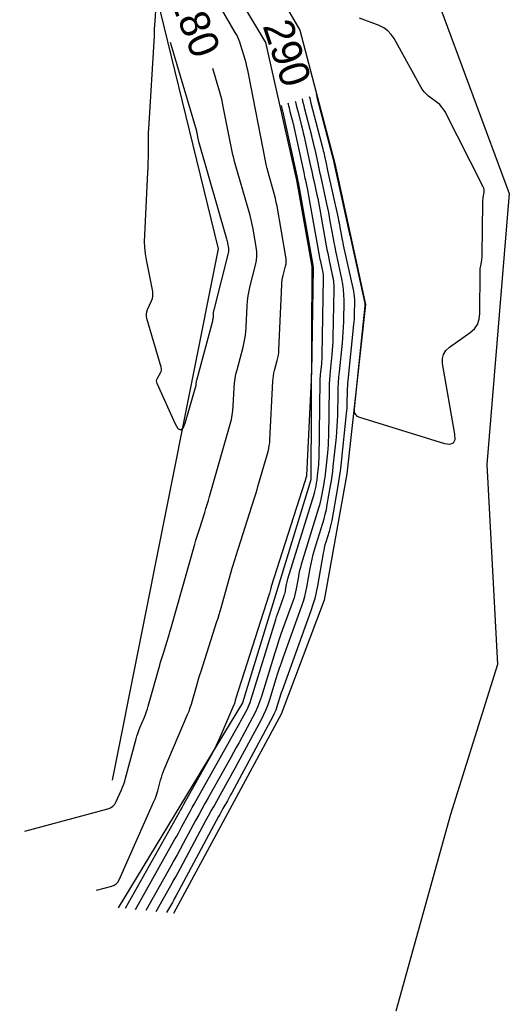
# Model space of a CAD drawing. Extents: x 1574966 to 1597594, y 720505 to 737840.
# Drawn here: x 1578135.8 to 1578233.6, y 723709.7 to 723907.8 of the extents above; entities that cross this region are included whole.
import ezdxf

# ---------------------------------------------------------------- set-up
doc = ezdxf.new("R2010")
doc.units = 0
for name, color, linetype in [('R_Contour Annot', 7, 'Continuous'), ('R_Contours', 7, 'Continuous'), ('S_BREAKLINE', 7, 'Continuous'), ('S_STREAM', 7, 'Continuous')]:
    doc.layers.add(name, color=color, linetype=linetype)

msp = doc.modelspace()

# ---------------------------------------------------------------- linework, layer by layer
at = {"layer": 'R_Contours'}
for points in [[(1578165.86, 723903.34), (1578171.09, 723885.58), (1578171.12, 723885.46), (1578171.15, 723885.35), (1578171.18, 723885.23), (1578171.2, 723885.11), (1578171.47, 723883.72), (1578171.5, 723883.61), (1578171.52, 723883.5), (1578171.55, 723883.38), (1578171.58, 723883.27), (1578177.13, 723864.01), (1578177.2, 723863.77), (1578177.25, 723863.54), (1578177.3, 723863.3), (1578177.35, 723863.07), (1578177.52, 723862.12), (1578177.54, 723861.88), (1578177.55, 723861.64), (1578177.53, 723861.41), (1578177.48, 723861.17), (1578174.57, 723849.86), (1578174.53, 723849.67), (1578174.49, 723849.48), (1578174.47, 723849.29), (1578174.46, 723849.1), (1578174.42, 723848.33), (1578174.41, 723848.13), (1578174.38, 723847.94), (1578174.35, 723847.75), (1578174.3, 723847.57), (1578171.09, 723835.72), (1578171.07, 723835.64), (1578171.05, 723835.55), (1578171.04, 723835.47), (1578171.04, 723835.38), (1578171.02, 723835.04), (1578171.01, 723834.95), (1578171, 723834.87), (1578170.98, 723834.78), (1578170.96, 723834.7), (1578168.8, 723827.12), (1578168.4, 723826.15), (1578167.97, 723825.8), (1578167.48, 723826.08), (1578166.95, 723826.99), (1578163.26, 723835.13), (1578163.17, 723835.4), (1578163.15, 723835.67), (1578163.2, 723835.94), (1578163.31, 723836.2), (1578163.91, 723837.26), (1578164.03, 723837.53), (1578164.09, 723837.8), (1578164.1, 723838.08), (1578164.04, 723838.37), (1578161.22, 723848.07), (1578161.13, 723848.53), (1578161.12, 723848.99), (1578161.19, 723849.44), (1578161.35, 723849.88), (1578162.15, 723851.65), (1578162.32, 723852.09), (1578162.41, 723852.54), (1578162.42, 723853.01), (1578162.37, 723853.48), (1578161.12, 723859.82), (1578160.92, 723861.04), (1578160.79, 723862.26), (1578160.74, 723863.49), (1578160.77, 723864.72), (1578161.41, 723877.34), (1578161.44, 723878.07), (1578161.46, 723878.79), (1578161.48, 723879.51), (1578161.49, 723880.23), (1578161.5, 723883.12), (1578161.51, 723883.84), (1578161.52, 723884.56), (1578161.55, 723885.28), (1578161.59, 723886.01), (1578162.71, 723904.54), (1578162.72, 723904.71), (1578162.73, 723904.88), (1578162.73, 723905.05), (1578162.74, 723905.23), (1578162.74, 723905.92), (1578162.75, 723906.09), (1578162.75, 723906.26), (1578162.76, 723906.44), (1578162.77, 723906.61), (1578163.05, 723910.49)], [(1578151.14, 723733.89), (1578154.21, 723734.72), (1578154.69, 723734.9), (1578155.09, 723735.17), (1578155.42, 723735.52), (1578155.67, 723735.97), (1578162.62, 723751.6), (1578162.84, 723752.12), (1578163.04, 723752.64), (1578163.21, 723753.17), (1578163.37, 723753.71), (1578163.95, 723755.88), (1578164.1, 723756.42), (1578164.27, 723756.95), (1578164.46, 723757.48), (1578164.67, 723758), (1578169.35, 723768.99), (1578169.63, 723769.67), (1578169.88, 723770.37), (1578170.12, 723771.06), (1578170.33, 723771.77), (1578171.13, 723774.61), (1578171.33, 723775.32), (1578171.54, 723776.03), (1578171.75, 723776.74), (1578171.97, 723777.44), (1578175.21, 723787.57), (1578175.43, 723788.25), (1578175.64, 723788.94), (1578175.84, 723789.62), (1578176.04, 723790.31), (1578178.28, 723798.22), (1578178.46, 723798.85), (1578178.65, 723799.48), (1578178.84, 723800.11), (1578179.04, 723800.73), (1578182.67, 723812.08), (1578182.87, 723812.69), (1578183.05, 723813.3), (1578183.23, 723813.91), (1578183.41, 723814.52), (1578185.43, 723821.56), (1578185.57, 723822.13), (1578185.68, 723822.7), (1578185.76, 723823.27), (1578185.81, 723823.86), (1578186.38, 723835.59), (1578186.42, 723836.12), (1578186.49, 723836.65), (1578186.59, 723837.17), (1578186.71, 723837.68), (1578187.27, 723839.74), (1578187.4, 723840.25), (1578187.49, 723840.78), (1578187.56, 723841.3), (1578187.6, 723841.83), (1578188.17, 723854.81), (1578188.2, 723855.28), (1578188.26, 723855.75), (1578188.34, 723856.22), (1578188.45, 723856.69), (1578188.92, 723858.53), (1578189.02, 723859), (1578189.06, 723859.46), (1578189.05, 723859.93), (1578189, 723860.4), (1578187.22, 723870.53), (1578187.07, 723871.3), (1578186.91, 723872.06), (1578186.72, 723872.82), (1578186.52, 723873.57), (1578185.65, 723876.58), (1578185.44, 723877.33), (1578185.25, 723878.09), (1578185.08, 723878.85), (1578184.92, 723879.61), (1578181.51, 723897.04), (1578181.36, 723897.74), (1578181.2, 723898.45), (1578181.02, 723899.15), (1578180.82, 723899.84), (1578180.01, 723902.61), (1578179.78, 723903.3), (1578179.52, 723903.97), (1578179.22, 723904.62), (1578178.87, 723905.25), (1578176.2, 723909.84)], [(1578195.06, 723892.94), (1578195.15, 723892.56), (1578195.16, 723892.54), (1578195.16, 723892.52), (1578195.17, 723892.5), (1578195.17, 723892.48), (1578195.19, 723892.39), (1578195.2, 723892.37), (1578195.2, 723892.35), (1578195.21, 723892.33), (1578195.21, 723892.31), (1578198.56, 723879.37), (1578198.57, 723879.33), (1578198.58, 723879.3), (1578198.59, 723879.26), (1578198.6, 723879.22), (1578198.63, 723879.08), (1578198.64, 723879.01), (1578198.66, 723878.94), (1578201.67, 723865.25), (1578201.68, 723865.21), (1578201.69, 723865.17), (1578201.69, 723865.14), (1578201.7, 723865.1), (1578201.73, 723864.95), (1578201.73, 723864.91), (1578201.74, 723864.87), (1578201.75, 723864.84), (1578201.76, 723864.8), (1578204.78, 723851.07), (1578204.79, 723851.03), (1578204.79, 723851), (1578204.79, 723850.96), (1578204.79, 723850.92), (1578204.79, 723850.77), (1578204.79, 723850.73), (1578204.79, 723850.7), (1578204.79, 723850.66), (1578204.78, 723850.62), (1578203.04, 723834), (1578203.04, 723833.99), (1578203.04, 723833.99), (1578203.04, 723833.98), (1578203.04, 723833.97), (1578203.04, 723833.93), (1578203.04, 723833.92), (1578203.04, 723833.91), (1578203.04, 723833.9), (1578203.04, 723833.89), (1578202.63, 723830.04), (1578202.65, 723829.45), (1578202.84, 723828.97), (1578203.2, 723828.61), (1578203.74, 723828.36), (1578220.69, 723823.16), (1578221.78, 723822.98), (1578222.5, 723823.23), (1578222.84, 723823.91), (1578222.8, 723825.02), (1578220.34, 723839.11), (1578220.29, 723840.08), (1578220.49, 723840.94), (1578220.96, 723841.7), (1578221.68, 723842.35), (1578225.83, 723845.3), (1578226.68, 723846.05), (1578227.29, 723846.93), (1578227.66, 723847.94), (1578227.79, 723849.07), (1578227.84, 723857.5), (1578227.84, 723857.78), (1578227.86, 723858.06), (1578227.9, 723858.34), (1578227.94, 723858.62), (1578228.14, 723859.74), (1578228.18, 723860.02), (1578228.21, 723860.3), (1578228.23, 723860.58), (1578228.24, 723860.87), (1578228.37, 723871.17), (1578228.37, 723871.44), (1578228.39, 723871.72), (1578228.42, 723872), (1578228.46, 723872.27), (1578228.62, 723873.37), (1578228.64, 723873.64), (1578228.62, 723873.9), (1578228.56, 723874.16), (1578228.45, 723874.41), (1578220.75, 723889.5), (1578220.47, 723889.98), (1578220.14, 723890.42), (1578219.76, 723890.83), (1578219.33, 723891.19), (1578217.52, 723892.55), (1578217.09, 723892.91), (1578216.7, 723893.3), (1578216.36, 723893.74), (1578216.06, 723894.22), (1578210.64, 723904.02), (1578210.07, 723904.87), (1578209.39, 723905.59), (1578208.58, 723906.16), (1578207.66, 723906.61), (1578203.72, 723908.1)], [(1578136.79, 723745.69), (1578153.37, 723750.16), (1578153.93, 723750.37), (1578154.4, 723750.69), (1578154.79, 723751.1), (1578155.08, 723751.62), (1578156.1, 723753.91), (1578156.34, 723754.49), (1578156.56, 723755.07), (1578156.76, 723755.66), (1578156.93, 723756.26), (1578159.03, 723764.1), (1578159.19, 723764.66), (1578159.37, 723765.22), (1578159.57, 723765.77), (1578159.79, 723766.31), (1578160.7, 723768.47), (1578160.93, 723769.01), (1578161.13, 723769.56), (1578161.31, 723770.12), (1578161.48, 723770.68), (1578163.76, 723778.81), (1578163.94, 723779.42), (1578164.12, 723780.03), (1578164.3, 723780.63), (1578164.49, 723781.24), (1578165.27, 723783.66), (1578165.46, 723784.27), (1578165.64, 723784.88), (1578165.82, 723785.49), (1578166, 723786.1), (1578170.79, 723803), (1578171.02, 723803.8), (1578171.26, 723804.6), (1578171.51, 723805.4), (1578171.76, 723806.19), (1578172.77, 723809.37), (1578173.02, 723810.16), (1578173.27, 723810.96), (1578173.51, 723811.76), (1578173.74, 723812.56), (1578177.87, 723827.01), (1578178.1, 723827.9), (1578178.28, 723828.79), (1578178.4, 723829.7), (1578178.47, 723830.61), (1578178.65, 723834.27), (1578178.72, 723835.18), (1578178.84, 723836.09), (1578179, 723836.99), (1578179.22, 723837.87), (1578180.44, 723842.36), (1578180.68, 723843.36), (1578180.86, 723844.37), (1578180.99, 723845.39), (1578181.07, 723846.42), (1578181.25, 723850.58), (1578181.32, 723851.6), (1578181.45, 723852.61), (1578181.62, 723853.61), (1578181.85, 723854.6), (1578182.92, 723858.76), (1578183.1, 723859.66), (1578183.19, 723860.56), (1578183.17, 723861.46), (1578183.06, 723862.36), (1578182.43, 723865.99), (1578182.25, 723866.9), (1578182.06, 723867.8), (1578181.84, 723868.69), (1578181.6, 723869.58), (1578178.75, 723879.46), (1578178.57, 723880.12), (1578178.4, 723880.79), (1578178.24, 723881.47), (1578178.1, 723882.15), (1578176.47, 723890.48), (1578176.33, 723891.19), (1578176.16, 723891.89), (1578175.98, 723892.59), (1578175.79, 723893.29), (1578174.39, 723898.03)], [(1578193.67, 723892.48), (1578193.75, 723892.15), (1578193.83, 723891.8), (1578193.91, 723891.46), (1578194, 723891.12), (1578196.37, 723881.97), (1578196.46, 723881.61), (1578196.55, 723881.26), (1578196.63, 723880.9), (1578196.71, 723880.54), (1578197.02, 723879.1), (1578197.1, 723878.74), (1578197.18, 723878.38), (1578197.26, 723878.02), (1578197.34, 723877.66), (1578199.44, 723868.12), (1578199.53, 723867.68), (1578199.62, 723867.23), (1578199.71, 723866.78), (1578199.79, 723866.33), (1578200.11, 723864.53), (1578200.19, 723864.08), (1578200.28, 723863.63), (1578200.37, 723863.19), (1578200.47, 723862.74), (1578202.49, 723853.55), (1578202.59, 723853), (1578202.67, 723852.45), (1578202.7, 723851.9), (1578202.71, 723851.35), (1578202.67, 723849.12), (1578202.66, 723848.56), (1578202.63, 723848), (1578202.59, 723847.45), (1578202.54, 723846.89), (1578201.37, 723835.72), (1578201.32, 723835.18), (1578201.28, 723834.63), (1578201.25, 723834.08), (1578201.24, 723833.53), (1578201.2, 723831.33), (1578201.19, 723830.78), (1578201.16, 723830.23), (1578201.12, 723829.68), (1578201.07, 723829.13), (1578200.04, 723819.4), (1578199.89, 723818.12), (1578199.72, 723816.83), (1578199.53, 723815.56), (1578199.32, 723814.28), (1578198.17, 723807.76), (1578198.06, 723807.2), (1578197.94, 723806.65), (1578197.8, 723806.1), (1578197.64, 723805.56), (1578196.97, 723803.4), (1578196.81, 723802.86), (1578196.67, 723802.31), (1578196.55, 723801.76), (1578196.44, 723801.21), (1578195.31, 723794.68), (1578195.06, 723793.42), (1578194.75, 723792.17), (1578194.39, 723790.93), (1578193.98, 723789.71), (1578188.22, 723773.76), (1578188.06, 723773.33), (1578187.92, 723772.9), (1578187.77, 723772.47), (1578187.64, 723772.03), (1578187.1, 723770.29), (1578186.96, 723769.86), (1578186.79, 723769.44), (1578186.61, 723769.03), (1578186.4, 723768.62), (1578178.17, 723753.33), (1578177.95, 723752.93), (1578177.74, 723752.54), (1578177.52, 723752.14), (1578177.3, 723751.75), (1578176.41, 723750.18), (1578176.19, 723749.79), (1578175.98, 723749.4), (1578175.76, 723749), (1578175.55, 723748.6), (1578167.06, 723732.84), (1578166.87, 723732.49), (1578166.68, 723732.15), (1578166.49, 723731.8), (1578166.3, 723731.46), (1578165.14, 723729.4)], [(1578188.08, 723890.63), (1578188.28, 723889.74), (1578188.29, 723889.68), (1578188.31, 723889.62), (1578188.32, 723889.55), (1578188.34, 723889.49), (1578188.4, 723889.24), (1578188.42, 723889.17), (1578188.43, 723889.11), (1578188.45, 723889.05), (1578188.46, 723888.98), (1578191.3, 723875.93), (1578191.31, 723875.88), (1578191.32, 723875.83), (1578191.33, 723875.79), (1578191.34, 723875.74), (1578191.39, 723875.55), (1578191.4, 723875.51), (1578191.4, 723875.46), (1578191.41, 723875.41), (1578191.42, 723875.37), (1578194.38, 723858.75), (1578194.39, 723858.7), (1578194.39, 723858.66), (1578194.4, 723858.62), (1578194.41, 723858.57), (1578194.45, 723858.4), (1578194.46, 723858.36), (1578194.46, 723858.32), (1578194.47, 723858.27), (1578194.47, 723858.23), (1578194.1, 723837.22), (1578194.1, 723837.21), (1578194.09, 723837.2), (1578194.09, 723837.19), (1578194.08, 723836.37), (1578194.08, 723836.24), (1578194.07, 723836.1), (1578194.07, 723835.96), (1578194.06, 723835.82), (1578193.12, 723816.72), (1578193.12, 723816.66), (1578193.11, 723816.6), (1578193.1, 723816.54), (1578193.08, 723816.48), (1578192.88, 723815.76), (1578192.86, 723815.69), (1578192.84, 723815.63), (1578192.82, 723815.57), (1578192.8, 723815.51), (1578186.08, 723794.53), (1578186.06, 723794.45), (1578186.03, 723794.37), (1578186.01, 723794.28), (1578185.99, 723794.2), (1578185.69, 723793.17), (1578185.67, 723793.08), (1578185.64, 723792.99), (1578185.61, 723792.9), (1578185.59, 723792.81), (1578179.01, 723772.26), (1578178.98, 723772.15), (1578178.95, 723772.04), (1578178.91, 723771.93), (1578178.88, 723771.82), (1578178.76, 723771.37), (1578178.72, 723771.26), (1578178.69, 723771.15), (1578178.65, 723771.05), (1578178.61, 723770.94), (1578176.01, 723764.85), (1578175.55, 723763.8), (1578175.06, 723762.77), (1578174.55, 723761.76), (1578174, 723760.76), (1578168.51, 723751), (1578168.44, 723750.87), (1578168.37, 723750.74), (1578168.3, 723750.61), (1578168.23, 723750.48), (1578167.95, 723749.96), (1578167.88, 723749.83), (1578167.8, 723749.7), (1578167.73, 723749.57), (1578167.66, 723749.44), (1578156.88, 723730.21)], [(1578158.95, 723730.01), (1578166.82, 723744.05), (1578167.17, 723744.68), (1578167.52, 723745.31), (1578167.87, 723745.95), (1578168.21, 723746.58), (1578169.58, 723749.13), (1578169.93, 723749.77), (1578170.28, 723750.4), (1578170.63, 723751.04), (1578170.98, 723751.67), (1578179.26, 723766.4), (1578179.51, 723766.85), (1578179.76, 723767.29), (1578180.01, 723767.74), (1578180.25, 723768.19), (1578181.22, 723770), (1578181.45, 723770.45), (1578181.66, 723770.92), (1578181.85, 723771.39), (1578182.01, 723771.88), (1578186.98, 723787.95), (1578187.14, 723788.49), (1578187.32, 723789.03), (1578187.5, 723789.56), (1578187.69, 723790.09), (1578188.65, 723792.74), (1578188.74, 723793.01), (1578188.82, 723793.28), (1578188.89, 723793.56), (1578188.94, 723793.84), (1578189.14, 723794.96), (1578189.19, 723795.24), (1578189.25, 723795.52), (1578189.32, 723795.8), (1578189.4, 723796.07), (1578194.7, 723813.23), (1578194.78, 723813.51), (1578194.86, 723813.79), (1578194.92, 723814.08), (1578194.98, 723814.37), (1578195.18, 723815.53), (1578195.23, 723815.82), (1578195.27, 723816.11), (1578195.31, 723816.4), (1578195.34, 723816.7), (1578195.53, 723818.4), (1578195.56, 723818.78), (1578195.59, 723819.17), (1578195.61, 723819.55), (1578195.62, 723819.93), (1578195.87, 723835.71), (1578195.88, 723836.13), (1578195.9, 723836.55), (1578195.93, 723836.97), (1578195.97, 723837.39), (1578196.15, 723839.07), (1578196.19, 723839.49), (1578196.22, 723839.92), (1578196.24, 723840.34), (1578196.25, 723840.76), (1578196.52, 723856.07), (1578196.52, 723856.46), (1578196.49, 723856.85), (1578196.44, 723857.23), (1578196.37, 723857.62), (1578196.03, 723859.14), (1578195.95, 723859.52), (1578195.87, 723859.91), (1578195.8, 723860.29), (1578195.73, 723860.67), (1578193.6, 723872.63), (1578193.53, 723873.02), (1578193.45, 723873.4), (1578193.38, 723873.79), (1578193.29, 723874.17), (1578192.96, 723875.7), (1578192.87, 723876.09), (1578192.79, 723876.47), (1578192.7, 723876.85), (1578192.62, 723877.24), (1578190.63, 723886.39), (1578190.55, 723886.77), (1578190.46, 723887.14), (1578190.37, 723887.52), (1578190.27, 723887.9), (1578189.88, 723889.41), (1578189.78, 723889.79), (1578189.69, 723890.16), (1578189.6, 723890.54), (1578189.52, 723890.92), (1578189.48, 723891.09)], [(1578190.88, 723891.55), (1578190.91, 723891.41), (1578191.08, 723890.71), (1578191.25, 723890.02), (1578191.42, 723889.33), (1578192.14, 723886.57), (1578192.31, 723885.87), (1578192.48, 723885.18), (1578192.64, 723884.49), (1578192.8, 723883.79), (1578193.94, 723878.55), (1578194.1, 723877.83), (1578194.25, 723877.11), (1578194.41, 723876.39), (1578194.57, 723875.67), (1578195.2, 723872.79), (1578195.36, 723872.06), (1578195.5, 723871.34), (1578195.64, 723870.62), (1578195.78, 723869.89), (1578197.07, 723862.6), (1578197.21, 723861.87), (1578197.35, 723861.15), (1578197.49, 723860.43), (1578197.65, 723859.71), (1578198.28, 723856.83), (1578198.42, 723856.11), (1578198.51, 723855.38), (1578198.57, 723854.65), (1578198.57, 723853.92), (1578198.4, 723844.29), (1578198.38, 723843.45), (1578198.34, 723842.61), (1578198.28, 723841.77), (1578198.2, 723840.94), (1578197.85, 723837.59), (1578197.77, 723836.75), (1578197.71, 723835.91), (1578197.67, 723835.07), (1578197.65, 723834.23), (1578197.49, 723824.49), (1578197.47, 723823.67), (1578197.43, 723822.85), (1578197.37, 723822.04), (1578197.29, 723821.23), (1578196.91, 723817.6), (1578196.84, 723816.98), (1578196.76, 723816.35), (1578196.66, 723815.73), (1578196.56, 723815.11), (1578196.12, 723812.64), (1578196.01, 723812.03), (1578195.87, 723811.42), (1578195.71, 723810.81), (1578195.54, 723810.21), (1578192.07, 723798.98), (1578191.9, 723798.38), (1578191.74, 723797.78), (1578191.61, 723797.18), (1578191.49, 723796.57), (1578191.06, 723794.12), (1578190.94, 723793.51), (1578190.8, 723792.91), (1578190.63, 723792.32), (1578190.43, 723791.73), (1578188.34, 723785.97), (1578187.93, 723784.81), (1578187.54, 723783.65), (1578187.15, 723782.48), (1578186.78, 723781.31), (1578184.09, 723772.59), (1578183.73, 723771.51), (1578183.31, 723770.45), (1578182.85, 723769.41), (1578182.33, 723768.4), (1578180.17, 723764.38), (1578179.63, 723763.38), (1578179.08, 723762.38), (1578178.53, 723761.38), (1578177.97, 723760.38), (1578173.44, 723752.33), (1578172.81, 723751.2), (1578172.18, 723750.06), (1578171.56, 723748.92), (1578170.94, 723747.78), (1578168.48, 723743.21), (1578167.86, 723742.07), (1578167.24, 723740.93), (1578166.61, 723739.79), (1578165.98, 723738.66), (1578161.01, 723729.8)], [(1578163.08, 723729.6), (1578165.99, 723734.8), (1578166.48, 723735.67), (1578166.96, 723736.54), (1578167.44, 723737.41), (1578167.91, 723738.28), (1578173.02, 723747.78), (1578173.55, 723748.76), (1578174.08, 723749.73), (1578174.62, 723750.7), (1578175.16, 723751.66), (1578177.33, 723755.52), (1578177.87, 723756.49), (1578178.41, 723757.46), (1578178.94, 723758.43), (1578179.46, 723759.4), (1578184.09, 723767.99), (1578184.58, 723768.96), (1578185.03, 723769.96), (1578185.42, 723770.97), (1578185.77, 723772.01), (1578187.06, 723776.19), (1578187.39, 723777.23), (1578187.73, 723778.27), (1578188.09, 723779.31), (1578188.45, 723780.34), (1578192.2, 723790.72), (1578192.51, 723791.62), (1578192.77, 723792.54), (1578193, 723793.47), (1578193.18, 723794.4), (1578193.84, 723798.17), (1578194.02, 723799.11), (1578194.23, 723800.04), (1578194.47, 723800.97), (1578194.73, 723801.89), (1578196.37, 723807.19), (1578196.64, 723808.11), (1578196.88, 723809.04), (1578197.09, 723809.97), (1578197.27, 723810.92), (1578197.94, 723814.7), (1578198.1, 723815.65), (1578198.24, 723816.59), (1578198.36, 723817.55), (1578198.47, 723818.5), (1578199.09, 723824.37), (1578199.2, 723825.45), (1578199.27, 723826.54), (1578199.33, 723827.63), (1578199.36, 723828.72), (1578199.43, 723833.09), (1578199.46, 723834.18), (1578199.51, 723835.27), (1578199.59, 723836.36), (1578199.69, 723837.44), (1578200.29, 723843.16), (1578200.39, 723844.23), (1578200.47, 723845.31), (1578200.52, 723846.38), (1578200.55, 723847.46), (1578200.63, 723851.77), (1578200.61, 723852.84), (1578200.54, 723853.91), (1578200.4, 723854.97), (1578200.2, 723856.03), (1578199.18, 723860.68), (1578198.99, 723861.53), (1578198.82, 723862.39), (1578198.65, 723863.25), (1578198.49, 723864.11), (1578197.88, 723867.56), (1578197.72, 723868.42), (1578197.56, 723869.28), (1578197.38, 723870.14), (1578197.2, 723871), (1578196.02, 723876.37), (1578195.87, 723877.06), (1578195.72, 723877.74), (1578195.57, 723878.43), (1578195.42, 723879.11), (1578194.82, 723881.85), (1578194.67, 723882.54), (1578194.51, 723883.22), (1578194.34, 723883.9), (1578194.17, 723884.58), (1578192.79, 723889.93), (1578192.62, 723890.59), (1578192.46, 723891.26), (1578192.3, 723891.92), (1578192.28, 723892.02)]]:
    msp.add_lwpolyline(points, dxfattribs=at)
at = {"layer": 'S_BREAKLINE'}
for p, q in [((1578175.55, 723862.03), (1578132.36, 724038.09)), ((1578218.43, 723914.14), (1578233.64, 723873.06)), ((1578233.64, 723873.06), (1578229.2, 723818.95)), ((1578154.34, 723755.9), (1578175.55, 723862.03)), ((1578229.2, 723818.95), (1578231.32, 723778.97)), ((1578231.32, 723778.97), (1578221.93, 723748.98)), ((1578221.93, 723748.98), (1578210.95, 723709.72))]:
    msp.add_line(p, q, dxfattribs=at)
at = {"layer": 'S_STREAM'}
for p, q in [((1578173.97, 723936.32), (1578191.78, 723905.69)), ((1578166.34, 723934.04), (1578184.93, 723903.27)), ((1578191.78, 723905.69), (1578198.8, 723879.08)), ((1578184.93, 723903.27), (1578191.12, 723875.75)), ((1578198.8, 723879.08), (1578204.94, 723850.89)), ((1578191.12, 723875.75), (1578194.21, 723858.5)), ((1578194.21, 723858.5), (1578193.96, 723815.9)), ((1578204.94, 723850.89), (1578201.2, 723817.06)), ((1578201.2, 723817.06), (1578196.66, 723791.8)), ((1578193.96, 723815.9), (1578180.32, 723771.3)), ((1578196.66, 723791.8), (1578188.05, 723769.07)), ((1578180.32, 723771.3), (1578155.44, 723730.36)), ((1578188.05, 723769.07), (1578166.5, 723729.26))]:
    msp.add_line(p, q, dxfattribs=at)

# ---------------------------------------------------------------- texts
at = {"layer": 'R_Contour Annot'}
for s, rotation, p in [('280', 291.4427, (1578165.62, 723912.15)), ('290', 288.3198, (1578184.3, 723906.59))]:
    msp.add_text(s, height=6, rotation=rotation, dxfattribs=at).set_placement(p)

doc.saveas('drawing.dxf')
